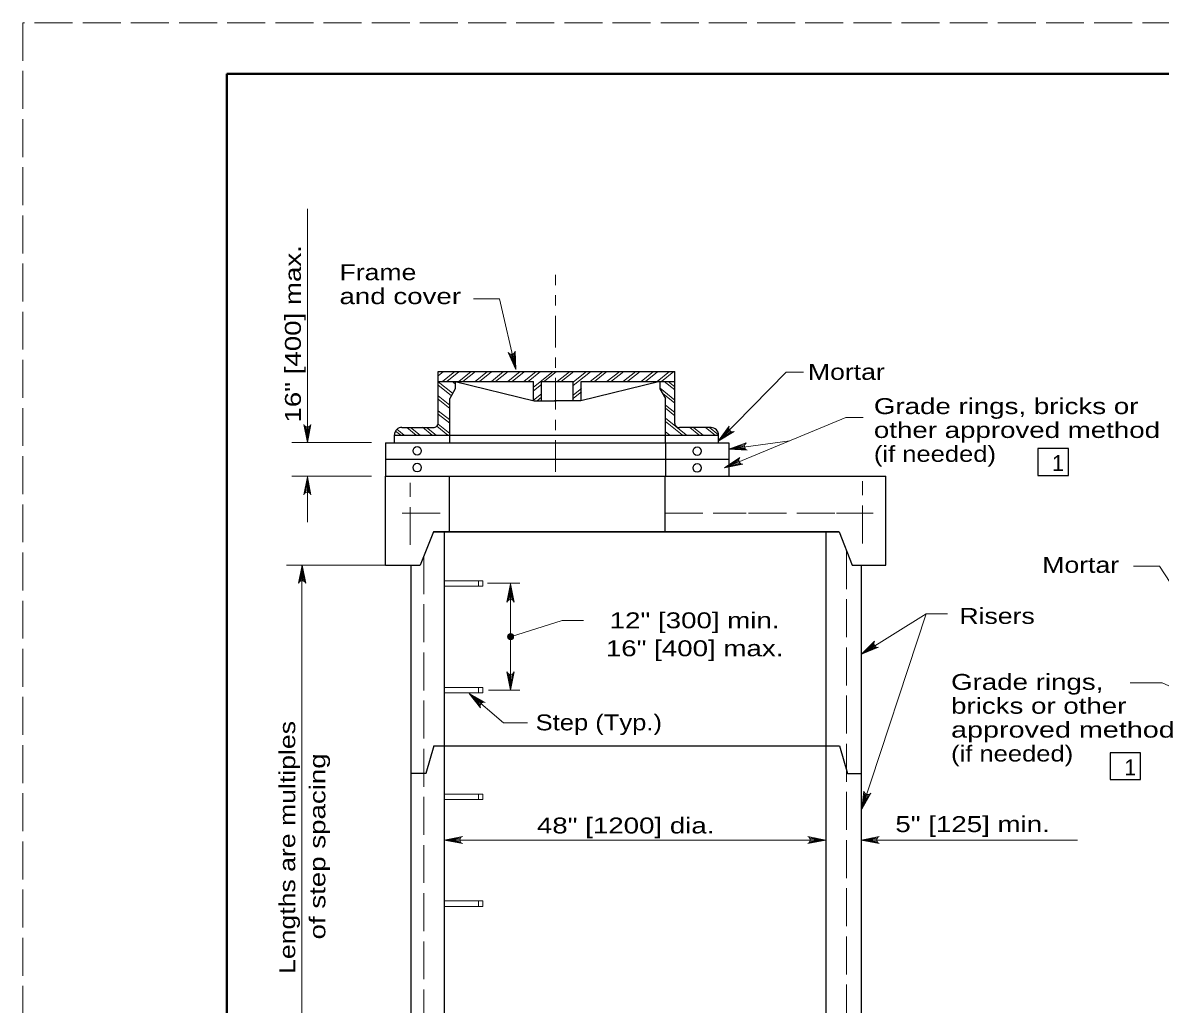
# Model space of a CAD drawing. Extents: x 808.4 to 842.4, y 1034.6 to 1056.6.
# Drawn here: x 808.44 to 819.59, y 1047.01 to 1056.63 of the extents above; entities that cross this region are included whole.
import ezdxf
from ezdxf.enums import TextEntityAlignment as Align

# ---------------------------------------------------------------- set-up
doc = ezdxf.new("R2010")
doc.units = 0
doc.header["$LTSCALE"] = 0.062
doc.linetypes.add('DOT_DASHED', pattern=[7.7, 5, -1.2, 0.3, -1.2])
doc.linetypes.add('LONG_DASHED', pattern=[7.5, 6, -1.5])
doc.layers.add('1', color=7, linetype='Continuous', lineweight=13)
doc.layers.add('10', color=7, linetype='Continuous')

msp = doc.modelspace()

# ---------------------------------------------------------------- hatches: boundary and pattern name
at = {"layer": '1'}
msp.add_hatch(color=256, dxfattribs=at).paths.add_polyline_path([(813.24917, 1050.61065, 1), (813.19017, 1050.61065, 1)])

# ---------------------------------------------------------------- linework, layer by layer
for p, q in [((811.22775, 1054.80258), (811.22775, 1052.5135)), ((813.22467, 1053.37817), (813.26942, 1053.2295)), ((813.23608, 1053.379), (813.26942, 1053.2295)), ((813.2495, 1053.38492), (813.26942, 1053.2295)), ((813.25833, 1053.39317), (813.26942, 1053.2295)), ((812.558, 1053.20617), (812.51225, 1053.16983)), ((812.674, 1053.20858), (812.55283, 1053.11225)), ((812.71342, 1053.20667), (812.59467, 1053.11225)), ((812.83183, 1053.20808), (812.71125, 1053.11225)), ((812.87442, 1053.20867), (812.75308, 1053.11225)), ((812.99392, 1053.20858), (812.87267, 1053.11225)), ((813.03333, 1053.20667), (812.9145, 1053.11225)), ((813.15167, 1053.20808), (813.03108, 1053.11225)), ((813.19425, 1053.20867), (813.07292, 1053.11225)), ((813.31367, 1053.20858), (813.19242, 1053.11225)), ((813.35308, 1053.20667), (813.23425, 1053.11225)), ((813.4715, 1053.20808), (813.35083, 1053.11225)), ((813.514, 1053.20867), (813.39275, 1053.11225)), ((813.63792, 1053.2085), (813.44475, 1053.05508)), ((813.67008, 1053.20867), (813.55125, 1053.11425)), ((813.79575, 1053.20792), (813.67483, 1053.11192)), ((813.83825, 1053.20858), (813.71667, 1053.11192)), ((814.00175, 1053.20658), (813.834, 1053.07325)), ((813.96233, 1053.2085), (813.83542, 1053.10767)), ((814.12017, 1053.20792), (814.0005, 1053.11292)), ((814.16275, 1053.20858), (814.04208, 1053.11275)), ((814.28883, 1053.21075), (814.16758, 1053.1145)), ((814.32825, 1053.20883), (814.20942, 1053.1145)), ((814.44658, 1053.21025), (814.326, 1053.1145)), ((814.48917, 1053.21092), (814.36783, 1053.1145)), ((814.62008, 1053.20858), (814.49883, 1053.11225)), ((814.6595, 1053.20667), (814.54067, 1053.11225)), ((814.77792, 1053.20808), (814.65725, 1053.11225)), ((814.82042, 1053.20867), (814.69917, 1053.11225)), ((812.51, 1053.1085), (812.65167, 1052.99608)), ((812.64642, 1053.11142), (812.67617, 1053.08783)), ((814.72558, 1053.111), (814.82842, 1053.02942)), ((814.76475, 1053.11175), (814.82917, 1053.06058)), ((812.51, 1053.07533), (812.63883, 1052.973)), ((813.52267, 1053.08358), (813.444, 1053.02117)), ((813.52267, 1052.99117), (813.44417, 1052.92875)), ((813.91358, 1053.044), (813.83475, 1052.98133)), ((813.91317, 1053.01033), (813.83508, 1052.94825)), ((814.68492, 1053.04475), (814.82942, 1052.92983)), ((814.711, 1052.993), (814.829, 1052.89925)), ((812.51, 1052.97025), (812.62392, 1052.87992)), ((812.51025, 1052.93692), (812.62392, 1052.84658)), ((813.52267, 1052.95775), (813.47858, 1052.92275)), ((814.737, 1052.88058), (814.82925, 1052.80725)), ((812.51075, 1052.792), (812.623, 1052.70283)), ((812.51125, 1052.82475), (812.62292, 1052.73625)), ((814.737, 1052.84875), (814.83017, 1052.77475)), ((815.31717, 1052.26558), (816.50617, 1052.76008)), ((816.50617, 1052.76008), (816.67592, 1052.76033)), ((811.20533, 1052.67375), (811.22775, 1052.5135)), ((811.21642, 1052.66833), (811.22775, 1052.5135)), ((811.2525, 1052.67567), (811.22775, 1052.5135)), ((811.24217, 1052.6695), (811.22775, 1052.5135)), ((811.22775, 1052.66667), (811.22775, 1052.5135)), ((812.10608, 1052.64375), (812.17742, 1052.58708)), ((812.20133, 1052.65992), (812.29567, 1052.585)), ((812.23925, 1052.65967), (812.33183, 1052.58617)), ((812.35492, 1052.663), (812.45233, 1052.58567)), ((812.39433, 1052.66208), (812.48908, 1052.58692)), ((812.49583, 1052.67317), (812.60508, 1052.58642)), ((812.50892, 1052.69392), (812.62308, 1052.60333)), ((814.737, 1052.75233), (814.94125, 1052.59008)), ((814.737, 1052.72058), (814.90175, 1052.5895)), ((814.97492, 1052.65967), (815.06408, 1052.58892)), ((815.01575, 1052.65917), (815.10667, 1052.58708)), ((815.13075, 1052.65958), (815.22317, 1052.58625)), ((815.16967, 1052.6595), (815.25658, 1052.59042)), ((815.35917, 1052.65167), (815.25542, 1052.5275)), ((812.0925, 1052.62475), (812.14358, 1052.58417)), ((814.73842, 1052.61758), (814.77875, 1052.5855)), ((815.36258, 1052.63975), (815.25542, 1052.5275)), ((815.369, 1052.63042), (815.25542, 1052.5275)), ((815.38067, 1052.6215), (815.25542, 1052.5275)), ((815.39225, 1052.618), (815.25542, 1052.5275)), ((815.35883, 1052.44983), (815.95525, 1052.53092)), ((811.07508, 1052.5135), (811.85642, 1052.5135)), ((815.5145, 1052.494), (815.35883, 1052.44983)), ((815.51067, 1052.48233), (815.35883, 1052.44983)), ((815.51058, 1052.47083), (815.35883, 1052.44983)), ((815.51525, 1052.45692), (815.35883, 1052.44983)), ((815.52283, 1052.44758), (815.35883, 1052.44983)), ((815.45675, 1052.34733), (815.31717, 1052.26558)), ((815.456, 1052.335), (815.31717, 1052.26558)), ((815.45883, 1052.32392), (815.31717, 1052.26558)), ((815.46692, 1052.31167), (815.31717, 1052.26558)), ((815.4765, 1052.30442), (815.31717, 1052.26558)), ((811.07508, 1052.18333), (811.85642, 1052.18333)), ((811.20292, 1052.01675), (811.22775, 1052.17892)), ((811.21333, 1052.02292), (811.22775, 1052.17892)), ((811.22775, 1052.17892), (811.22775, 1051.73408)), ((811.22775, 1052.02575), (811.22775, 1052.17892)), ((811.23908, 1052.02408), (811.22775, 1052.17892)), ((811.25017, 1052.01867), (811.22775, 1052.17892)), ((811.024, 1051.31167), (812.11758, 1051.31167)), ((811.15183, 1051.14958), (811.17667, 1051.31167)), ((811.16225, 1051.15567), (811.17667, 1051.31167)), ((811.17467, 1051.31167), (811.17467, 1046.23342)), ((811.17667, 1051.1585), (811.17667, 1051.31167)), ((811.188, 1051.15683), (811.17667, 1051.31167)), ((811.19908, 1051.15142), (811.17667, 1051.31167)), ((812.57058, 1051.159), (812.94867, 1051.159)), ((812.57058, 1051.106), (812.94867, 1051.106)), ((812.90492, 1051.10592), (812.90492, 1051.15883)), ((812.94867, 1051.106), (812.94867, 1051.159)), ((812.99492, 1051.13658), (813.30858, 1051.13658)), ((813.19492, 1050.965), (813.21967, 1051.12717)), ((813.20525, 1050.97117), (813.21967, 1051.12717)), ((813.21967, 1051.12717), (813.21967, 1050.08808)), ((813.21967, 1050.974), (813.21967, 1051.12717)), ((813.231, 1050.97233), (813.21967, 1051.12717)), ((813.24208, 1050.96692), (813.21967, 1051.12717)), ((816.65725, 1050.43992), (817.29375, 1050.83308)), ((816.77967, 1050.54583), (816.65725, 1050.43992)), ((816.78108, 1050.5335), (816.65725, 1050.43992)), ((816.78592, 1050.52317), (816.65725, 1050.43992)), ((816.79608, 1050.51258), (816.65725, 1050.43992)), ((816.80683, 1050.50717), (816.65725, 1050.43992)), ((813.19725, 1050.24833), (813.21967, 1050.08808)), ((813.20833, 1050.24292), (813.21967, 1050.08808)), ((813.24442, 1050.25017), (813.21967, 1050.08808)), ((813.23408, 1050.24408), (813.21967, 1050.08808)), ((813.21967, 1050.24125), (813.21967, 1050.08808)), ((812.57058, 1050.11283), (812.94867, 1050.11283)), ((812.90492, 1050.05983), (812.90492, 1050.11283)), ((812.94867, 1050.05992), (812.94867, 1050.11283)), ((813.00308, 1050.08808), (813.30858, 1050.08808)), ((812.57058, 1050.05992), (812.94867, 1050.05992)), ((812.92967, 1049.95425), (812.81283, 1050.05325)), ((812.9225, 1049.94142), (812.81283, 1050.05325)), ((812.9205, 1049.92958), (812.81283, 1050.05325)), ((812.93825, 1049.96183), (812.81283, 1050.05325)), ((812.94958, 1049.96675), (812.81283, 1050.05325)), ((812.39125, 1049.2685), (812.25508, 1049.2685)), ((816.68992, 1049.07808), (816.66133, 1048.91883)), ((812.57058, 1049.06667), (812.94867, 1049.06667)), ((812.57058, 1049.01375), (812.94867, 1049.01375)), ((812.90492, 1049.01392), (812.90492, 1049.06692)), ((812.94867, 1049.01375), (812.94867, 1049.06667)), ((816.69875, 1049.0695), (816.66133, 1048.91883)), ((816.73533, 1049.06517), (816.66133, 1048.91883)), ((816.709, 1049.06442), (816.66133, 1048.91883)), ((816.72358, 1049.06258), (816.66133, 1048.91883)), ((812.73, 1048.64033), (812.56975, 1048.61792)), ((812.72458, 1048.62925), (812.56975, 1048.61792)), ((816.1485, 1048.64033), (816.30875, 1048.61792)), ((816.15392, 1048.62925), (816.30875, 1048.61792)), ((816.8145, 1048.64033), (816.65425, 1048.61792)), ((816.80908, 1048.62925), (816.65425, 1048.61792)), ((812.56975, 1048.61792), (815.24075, 1048.61792)), ((812.72292, 1048.61792), (812.56975, 1048.61792)), ((812.72575, 1048.6035), (812.56975, 1048.61792)), ((812.73183, 1048.59317), (812.56975, 1048.61792)), ((815.24075, 1048.61792), (816.30875, 1048.61792)), ((816.14658, 1048.59317), (816.30875, 1048.61792)), ((816.15275, 1048.6035), (816.30875, 1048.61792)), ((816.15558, 1048.61792), (816.30875, 1048.61792)), ((816.80742, 1048.61792), (816.65425, 1048.61792)), ((816.81025, 1048.6035), (816.65425, 1048.61792)), ((816.81642, 1048.59317), (816.65425, 1048.61792)), ((816.65425, 1048.61792), (818.77375, 1048.61792)), ((812.57058, 1048.02058), (812.94867, 1048.02058)), ((812.57058, 1047.96767), (812.94867, 1047.96767)), ((812.90417, 1047.96808), (812.90417, 1048.021)), ((812.94867, 1047.96767), (812.94867, 1048.02058))]:
    msp.add_line(p, q, dxfattribs=at)
at = {"layer": '1', "linetype": 'DOT_DASHED'}
msp.add_line((813.6595, 1052.22617), (813.6595, 1054.1555), dxfattribs=at)
at = {"layer": '1', "lineweight": 25}
for p, q in [((812.51, 1052.70325), (812.51, 1053.20867)), ((812.51, 1053.20867), (814.83008, 1053.20867)), ((814.82917, 1052.70033), (814.82917, 1053.20867)), ((812.51, 1053.11225), (813.44508, 1053.11225)), ((812.67667, 1053.11033), (812.67667, 1053.03967)), ((813.44475, 1052.92433), (813.44475, 1053.11225)), ((813.52242, 1052.922), (813.52242, 1053.11225)), ((813.52242, 1053.11225), (813.83383, 1053.11225)), ((813.83383, 1052.922), (813.83383, 1053.11225)), ((813.91283, 1052.922), (813.91283, 1053.11225)), ((813.91283, 1053.11225), (814.83008, 1053.11225)), ((814.68358, 1053.11033), (814.68358, 1053.03967)), ((812.67667, 1053.03967), (812.62283, 1052.94433)), ((814.68358, 1053.03967), (814.73742, 1052.94433)), ((812.62283, 1052.50783), (812.62283, 1052.94433)), ((814.73742, 1052.50783), (814.73742, 1052.94433)), ((812.15533, 1052.66233), (812.46342, 1052.66233)), ((815.18392, 1052.6595), (814.87575, 1052.6595)), ((812.08133, 1052.51525), (812.08133, 1052.58758)), ((812.08342, 1052.58567), (815.25833, 1052.58567)), ((815.25783, 1052.51242), (815.25783, 1052.58475)), ((811.99433, 1052.51125), (811.99433, 1052.18542)), ((811.99433, 1052.51125), (815.35883, 1052.51125)), ((814.73742, 1052.50783), (814.73742, 1052.18542)), ((815.35883, 1052.51125), (815.35883, 1052.18542)), ((811.99433, 1052.3515), (815.35767, 1052.3515)), ((811.99433, 1052.18542), (816.41417, 1052.18542)), ((811.99433, 1052.18542), (815.35883, 1052.18542)), ((812.61867, 1052.18558), (812.61867, 1052.00083)), ((814.73175, 1052.17775), (814.73175, 1051.63983)), ((816.41417, 1052.18542), (816.896, 1052.18542)), ((812.61867, 1052.00083), (812.61867, 1051.64908)), ((812.4635, 1051.63983), (812.33508, 1051.31108)), ((812.4635, 1051.63983), (816.43808, 1051.63983)), ((812.46392, 1051.63983), (816.43875, 1051.63983)), ((812.56975, 1051.63983), (812.56975, 1040.02425)), ((816.30875, 1051.64075), (816.30875, 1046.22608)), ((816.43808, 1051.63983), (816.5665, 1051.31108)), ((816.43817, 1051.63975), (816.5665, 1051.31108)), ((811.99433, 1051.31108), (812.33508, 1051.31108)), ((812.24142, 1051.31108), (812.24142, 1046.22592)), ((816.5665, 1051.31108), (816.896, 1051.31108)), ((816.65425, 1051.31108), (816.65425, 1046.22608)), ((812.46817, 1049.54175), (816.44308, 1049.54175)), ((816.52008, 1049.2685), (816.65617, 1049.2685))]:
    msp.add_line(p, q, dxfattribs=at)
at = {"layer": '1', "linetype": 'LONG_DASHED'}
for p, q in [((812.15792, 1051.82225), (812.61725, 1051.82225)), ((814.73175, 1051.82225), (815.527, 1051.82225)), ((815.55225, 1051.82225), (816.41417, 1051.82225)), ((816.41417, 1051.82225), (816.77383, 1051.82225)), ((816.5125, 1051.44942), (816.5125, 1046.37117)), ((812.37008, 1051.40067), (812.37008, 1046.4815))]:
    msp.add_line(p, q, dxfattribs=at)
msp.add_lwpolyline([(808.43883, 1034.62767), (842.43883, 1034.62767), (842.43883, 1056.62767), (808.43883, 1056.62767)], close=True, dxfattribs=at)
at = {"layer": '1', "lineweight": 25}
for points in [[(810.43883, 1056.12767), (841.93883, 1056.12767), (841.93883, 1035.12767), (810.43883, 1035.12767)], [(818.38742, 1052.45358), (818.38742, 1052.192), (818.686, 1052.192), (818.686, 1052.45358)], [(819.09508, 1049.47108), (819.09508, 1049.2095), (819.39367, 1049.2095), (819.39367, 1049.47108)]]:
    msp.add_lwpolyline(points, close=True, dxfattribs=at)
at = {"layer": '1', "lineweight": 40}
msp.add_lwpolyline([(810.43883, 1056.12767), (841.93883, 1056.12767), (841.93883, 1035.12767), (810.43883, 1035.12767)], close=True, dxfattribs=at)
at = {"layer": '1'}
for points in [[(813.21267, 1053.38108), (813.26942, 1053.2295), (813.11108, 1053.921), (812.8565, 1053.921)], [(813.26542, 1053.41), (813.26942, 1053.2295), (813.19633, 1053.39458)], [(815.25783, 1052.52775), (815.92008, 1053.20408), (816.08983, 1053.20433)], [(811.26317, 1052.6905), (811.22775, 1052.5135), (811.19233, 1052.6905)], [(815.41042, 1052.62), (815.25542, 1052.5275), (815.363, 1052.67258)], [(815.53908, 1052.439), (815.35883, 1052.44983), (815.52933, 1052.50925)], [(815.49433, 1052.30025), (815.31717, 1052.26558), (815.46733, 1052.36567)], [(811.19233, 1052.00192), (811.22775, 1052.17892), (811.26317, 1052.00192)], [(811.14125, 1051.13467), (811.17667, 1051.31167), (811.21208, 1051.13467)], [(820.42717, 1050.00117), (819.57933, 1051.30342), (819.32275, 1051.30342)], [(813.18425, 1050.95017), (813.21967, 1051.12717), (813.25508, 1050.95017)], [(813.21967, 1050.61067), (813.72483, 1050.76925), (813.93467, 1050.76925)], [(816.66133, 1048.91883), (817.29375, 1050.83308), (817.50042, 1050.83308)], [(816.82508, 1050.50633), (816.65725, 1050.43992), (816.78667, 1050.56583)], [(813.25508, 1050.26508), (813.21967, 1050.08808), (813.18425, 1050.26508)], [(820.21367, 1049.88767), (819.60567, 1050.15742), (819.29283, 1050.15742)], [(812.81283, 1050.05325), (813.14867, 1049.76733), (813.38525, 1049.76733)], [(812.925, 1049.91183), (812.81283, 1050.05325), (812.97075, 1049.96583)], [(816.75008, 1049.076), (816.66133, 1048.91883), (816.68275, 1049.09808)], [(812.74675, 1048.5825), (812.56975, 1048.61792), (812.74675, 1048.65333)], [(816.13175, 1048.5825), (816.30875, 1048.61792), (816.13175, 1048.65333)], [(816.83125, 1048.5825), (816.65425, 1048.61792), (816.83125, 1048.65333)]]:
    msp.add_lwpolyline(points, dxfattribs=at)
at = {"layer": '1', "lineweight": 25}
for points in [[(812.67667, 1053.11033), (813.45225, 1052.92192), (813.66542, 1052.92192)], [(814.68358, 1053.11033), (813.908, 1052.92192), (813.65117, 1052.92192)], [(811.99433, 1051.31108), (811.99433, 1052.00083), (811.99433, 1052.18542)], [(816.896, 1051.31108), (816.896, 1052.00083), (816.896, 1052.18542)], [(816.43842, 1051.63983), (812.4635, 1051.63983), (812.33508, 1051.31108)], [(812.46817, 1049.54175), (812.3905, 1049.2685), (812.24142, 1049.2685)], [(816.44308, 1049.54175), (816.52075, 1049.2685), (816.65417, 1049.2685)]]:
    msp.add_lwpolyline(points, dxfattribs=at)
at = {"layer": '1', "linetype": 'LONG_DASHED'}
for points in [[(812.2345, 1051.50942), (812.2345, 1052.00083), (812.2345, 1052.12)], [(816.66767, 1051.52542), (816.66767, 1052.00083), (816.66767, 1052.136)]]:
    msp.add_lwpolyline(points, dxfattribs=at)
at = {"layer": '1'}
msp.add_circle((813.21967, 1050.61065), 0.0295, dxfattribs=at)
for centre, start, end in [((813.22772, 1053.41622), 214.66476, 350.49089), ((811.2277, 1052.70482), 202.08782, 337.91395), ((815.39723, 1052.65591), 154.21548, 290.04161), ((815.54833, 1052.47613), 119.98565, 255.81178), ((815.49403, 1052.33847), 134.46568, 270.29181), ((811.22777, 1051.98759), 22.08782, 157.91395), ((811.17669, 1051.12038), 22.08782, 157.91395), ((813.21971, 1050.93585), 22.08782, 157.91395), ((816.81787, 1050.54388), 144.99409, 280.82021), ((813.21963, 1050.27937), 202.08782, 337.91395), ((812.95878, 1049.92963), 71.81346, 207.63959), ((816.72083, 1049.10064), 183.95647, 319.7826), ((812.76102, 1048.61796), 112.08782, 247.91395), ((816.11746, 1048.61796), 292.08605, 67.91218), ((816.84555, 1048.61796), 112.08782, 247.91395)]:
    msp.add_arc(centre, 0.0382, start, end, dxfattribs=at)
at = {"layer": '1', "lineweight": 25}
for centre, major_axis, start_param, end_param in [((812.15191, 1052.58774), (0, 0.0747), 6.23518017, 7.85629289), ((812.46864, 1052.70588), (0, -0.04387), 6.1570556, 7.79212712), ((814.87053, 1052.70305), (0, -0.04387), 4.7742435, 6.40931502), ((815.18727, 1052.58491), (0, 0.0747), 4.71007773, 6.33119044)]:
    msp.add_ellipse(centre, major_axis=major_axis, ratio=0.944544, start_param=start_param, end_param=end_param, dxfattribs=at)
for centre in [(812.30437, 1052.43149), (815.04747, 1052.42808), (812.30437, 1052.26767), (815.04747, 1052.26425)]:
    msp.add_ellipse(centre, major_axis=(0, 0.04232), ratio=0.944544, dxfattribs=at)

# ---------------------------------------------------------------- texts
at = {"layer": '1'}
for p in [(818.52617, 1052.2345), (819.23383, 1049.252)]:
    msp.add_text('1', height=0.156, dxfattribs=at).set_placement(p)
at = {"layer": '10'}
for s, width, p in [('16" [400] max.', 1.3, (811.1645, 1052.709)), ('Lengths are multiples', 1.25, (811.10892, 1047.30567)), ('of step spacing', 1.3, (811.40408, 1047.64342))]:
    msp.add_text(s, height=0.156, rotation=90, dxfattribs=dict(at, width=width)).set_placement(p)
for s, width, p in [('Frame', 1.25, (811.543, 1054.10458)), ('and cover', 1.3, (811.543, 1053.86992)), ('Mortar', 1.25, (816.13342, 1053.12792)), ('Grade rings, bricks or', 1.3, (816.77992, 1052.79225)), ('other approved method', 1.3, (816.77992, 1052.55825)), ('(if needed)', 1.2, (816.77992, 1052.32425)), ('Mortar', 1.25, (818.42975, 1051.23642)), ('Risers', 1.25, (817.61758, 1050.73567)), ('Grade rings, ', 1.3, (817.53625, 1050.08933)), ('bricks or other ', 1.3, (817.53625, 1049.85533)), ('Step (Typ.)', 1.2, (813.46508, 1049.69258)), ('approved method ', 1.35, (817.53625, 1049.62133)), ('(if needed)', 1.2, (817.53625, 1049.38733)), ('5" [125] min.', 1.3, (816.99025, 1048.69567)), ('48" [1200] dia.', 1.3, (813.47742, 1048.682))]:
    msp.add_text(s, height=0.156, dxfattribs=dict(at, width=width)).set_placement(p)
at = {"layer": '10', "width": 1.3}
for s, p in [('12" [300] min.', (815.02304, 1050.693)), ('16" [400] max.', (815.023, 1050.419))]:
    msp.add_text(s, height=0.156, dxfattribs=at).set_placement(p, align=Align.CENTER)

doc.saveas('drawing.dxf')
